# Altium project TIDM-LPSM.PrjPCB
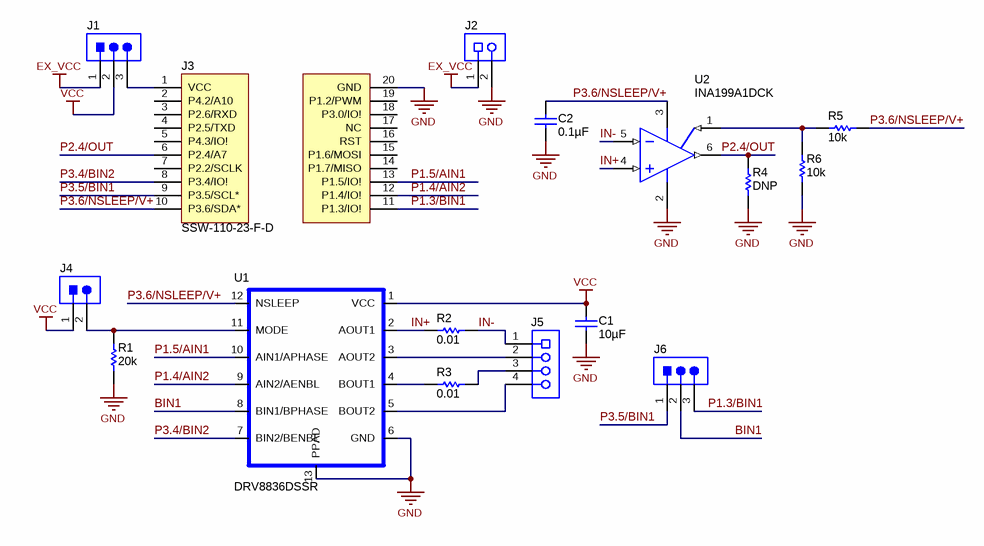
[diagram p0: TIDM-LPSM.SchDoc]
CopyrightYear: 2014; PCB_Layout: Who did the Layout?; PCB_Rev: E1; PRJ_Customer: Public Release; PRJ_Engineer: Enter name of project lead; PRJ_Number: XX####; PRJ_Title: Change in menu Project|Project Options|Parameters; SCH_Rev: E1; TechSupport: http://www.ti.com/support
1 sheet, 16 parts. Net scope: global (net labels, ports and power ports of the same name join across sheets).
Board file: TIDM-LPSM.PcbDoc

## Sheet TIDM-LPSM.SchDoc
size 431 x 279 mm; Date: Not shown in title block; ApprovedBy: Not shown in title block; CheckedBy: Not shown in title block; Author: Not shown in title block; CompanyName: Not shown in title block; Engineer: Not shown in title block; Organization: Not shown in title block; Address1: Not shown in title block; Address2: Not shown in title block; Address3: Not shown in title block; Address4: Not shown in title block; DocumentNumber: 1; Revision: Use project parameter SCH_Rev; SheetNumber: 1; SheetTotal: 1; PageSetup: Record=PageOptions|CenterHorizontal=True|CenterVertical=True|PrintScale=0.64|XCorrection=1.00|YCorrection=1.00|PrintKind=0|BorderSize=5000000|LeftOffset=0|BottomOffset=0|Orientation=2|PaperLength=1000|PaperWidth=1000|Scale=100|PaperSource=15|PrintQuality=600|MediaType=1|DitherType=10|PaperKind=Letter|PrintScaleMode=1

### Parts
C1  ValueDisplayed: 10µF  [0805_HV]  (hidden comment: C0805C106K9PAC)
C2  ValueDisplayed: 0.1µF  [0603]  (hidden comment: 0603YC104JAT2A)
J1  5-146278-3  [TE_5-146278-3]  (value not drawn)
J2  282841-2  [TEC_282841-2]  (value not drawn)
J3  SSW-110-23-F-D  [SSW-110-23-F-S]
J4  5-146278-2  [TE_5-146278-2]  (value not drawn)
J5  39544-3004  [MOLEX_39544-3004]  (value not drawn)
J6  5-146278-3  [TE_5-146278-3]  (value not drawn)
R1  value 20k  [0603]  (hidden comment: CRCW060320K0JNEA)
R2  value 0.01  [2512M]  (hidden comment: CRA2512-FZ-R010ELF)
R3  value 0.01  [2512M]  (hidden comment: CRA2512-FZ-R010ELF)
R4  value DNP  [0402]  (hidden comment: CRCW040210K0JNED)
R5  value 10k  [0402]  (hidden comment: CRCW040210K0JNED)
R6  value 10k  [0402]  (hidden comment: CRCW040210K0JNED)
U1  DRV8836DSSR  [DSS-12P]
U2  INA199A1DCK  [DCK0006A_N]

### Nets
EX_VCC: J1.1 J2.1
GND: C1.2 C2.2 J2.2 J3.20(GND) R1.1 R4.1 R6.1 U1.6(GND) U1.13(PPAD) U2.2(GND)
VCC: C1.1 J1.2 J4.1 U1.1(VCC)
BIN1: J6.2 U1.8(BIN1/BPHASE)
IN+: R2.1 U1.2(AOUT1) U2.4(IN+)
IN-: J5.1 R2.2 U2.5(IN-)
P1.3/BIN1: J3.11(P1.3/IO!) J6.3
P1.4/AIN2: J3.12(P1.4/IO!) U1.9(AIN2/AENBL)
P1.5/AIN1: J3.13(P1.5/IO!) U1.10(AIN1/APHASE)
P2.4/OUT: J3.6(P2.4/A7) R4.2 U2.6(OUT)
P3.4/BIN2: J3.8(P3.4/IO!) U1.7(BIN2/BENBL)
P3.5/BIN1: J3.9(P3.5/SCL*) J6.1
P3.6/NSLEEP/V+: C2.1 J3.10(P3.6/SDA*) R5.1 U1.12(NSLEEP) U2.3(VCC)
NetJ1_3: J1.3 J3.1(VCC)
NetJ4_2: J4.2 R1.2 U1.11(MODE)
NetJ5_2: J5.2 U1.3(AOUT2)
NetJ5_3: J5.3 R3.2
NetJ5_4: J5.4 U1.5(BOUT2)
NetR3_1: R3.1 U1.4(BOUT1)
NetR5_2: R5.2 R6.2 U2.1(REF)

Not connected (* = marked no-connect by the designer): J3 2(P4.2/A10) 3(P2.6/RXD) 4(P2.5/TXD) 5(P4.3/IO!) 7(P2.2/SCLK) 14(P1.7/MISO) 15(P1.6/MOSI) 16(RST) 17(NC) 18(P3.0/IO!) 19(P1.2/PWM)

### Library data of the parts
C1 = C0805C106K9PAC: CAP, CERM, 10uF, 6.3V, +/-10%, X5R, 0805; Manufacturer: Kemet; Polarized: N; CompType: Capacitor; U/M: EA; Cap_F: 0.00001; Tolerance_%: 10; Value1: Unknown; VDC_V: 6.3; TaMin_C: -55; TaMax_C: 85; Cap_Case: 0805
C2 = 0603YC104JAT2A: CAP, CERM, 0.1uF, 16V, +/-5%, X7R, 0603; Manufacturer: AVX; Polarized: N; CompType: Capacitor; U/M: EA; Cap_F: 0.0000001; Tolerance_%: 5; ESR_Ohm: 0.039; Value1: 0.039 ohm; VDC_V: 16; TaMin_C: -55; TaMax_C: 125
J1 J6 = 5-146278-3: Header, 100mil, 3x1, Tin, TH; Manufacturer: TE Connectivity; SymbolCreator: a0799628; U/M: EA
J2 = 282841-2: Terminal Block, 2x1, 5.08mm, TH; Manufacturer: TE Connectivity; SymbolCreator: a0412235; U/M: EA
J3 = MSP-EXP430FR5969 2x10 Header: Manufacturer: Used in BOM report; SymbolVersion: use current date i.e. 2008-05-20; SymbolCreator: Use a-id; CompType: Used in some BOM reports.  Useful for finding later.; U/M: EA, IN, or GM
J4 = 5-146278-2: Header, 100mil, 2x1, Tin, TH; Manufacturer: TE Connectivity; SymbolCreator: a0412235; U/M: EA
J5 = 39544-3004: Terminal Block, 4x1, 5.08mm, TH; Manufacturer: Molex; SymbolCreator: a0411947; U/M: EA
R1 = CRCW060320K0JNEA: RES, 20k ohm, 5%, 0.1W, 0603; Manufacturer: Vishay-Dale; CompType: Resistor; Res_ohm: 20000; Value_Code: 20k0; Tolerance_%: 5; Power_W: 0.1; VDC_V: 75; TempCo: 200 ppm/C; EIA_Code: E24; U/M: EA
R2 R3 = CRA2512-FZ-R010ELF: RES, 0.01 ohm, 1%, 3W, 2512; Manufacturer: Bourns; CompType: Resistor; Value_Code: R010; Tolerance_%: 1; Power_W: 3; TempCo: 75 ppm/C; EIA_Code: E96; U/M: EA
R4-R6 = CRCW040210K0JNED: RES, 10k ohm, 5%, 0.063W, 0402; Manufacturer: Vishay-Dale; CompType: Resistor; Res_ohm: 10000; Value_Code: 10k0; Tolerance_%: 5; Power_W: 0.063; VDC_V: 50; TempCo: 200 ppm/C; EIA_Code: E24; U/M: EA
U1 = DRV8835DSSR: IC, DUAL LOW VOLTAGE H-BRIDGE; Manufacturer: TI; Alternate Manufacturer: None; Area: 33856
U2 = INA199A1DCK: Voltage Output, High or Low Side Measurement, Bi-Directional Zerø-Drift Series Current-Shunt Monitor, DCK0006A; Alternate Manufacturer: None; Manufacturer: Texas Instruments; SymbolCreator: a0411947; CompType: IC; U/M: EA

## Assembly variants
001: not fitted FID1 FID2 FID3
